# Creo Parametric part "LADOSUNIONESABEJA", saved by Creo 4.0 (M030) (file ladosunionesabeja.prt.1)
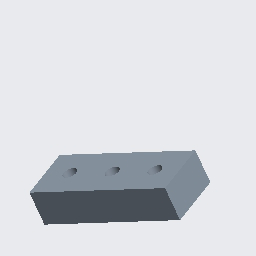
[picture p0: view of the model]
Units: millimeter Newton Second (mmNs); MM, TONNE, SECS

Created from: MMNS_PART_SOLID.PRT

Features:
  1. datum plane "RIGHT"
  2. datum plane "TOP"
  3. datum plane "FRONT"
  4. coordinate system
  5. sketch "Sketch 1"
  6. extrusion "Extrude 1"
  7. pattern "Pattern 1"
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
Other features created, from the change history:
  hole "Hole 1"
  hole "Hole 1 [2]"
  hole "Hole 1 [3]"

Surfaces: 9 plane, 3 cylinder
